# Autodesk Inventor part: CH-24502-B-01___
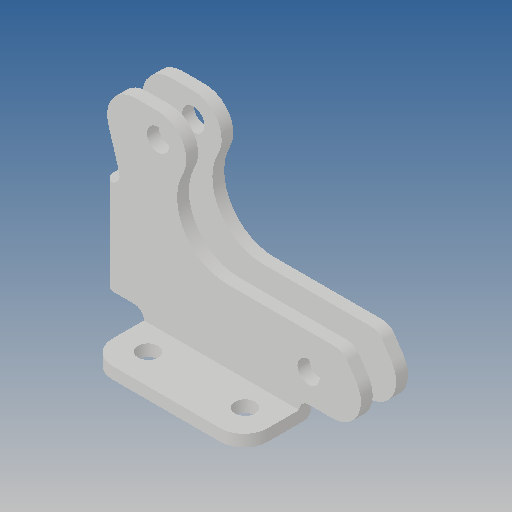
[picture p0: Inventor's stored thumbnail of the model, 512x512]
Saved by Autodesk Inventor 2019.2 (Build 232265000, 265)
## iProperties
Created: 2010-06
Part Number: CH-24502-B-01___
Material: Ogólny
Document SubType Name: Modeling
Designer: CADENGINEERING4
Density: 1 g/cm^3
Appearance: Domyślna
Author: CADENGINEERING4
Revision Number: ANY
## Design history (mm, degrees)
feature "NONE"
node "Bryła1"
